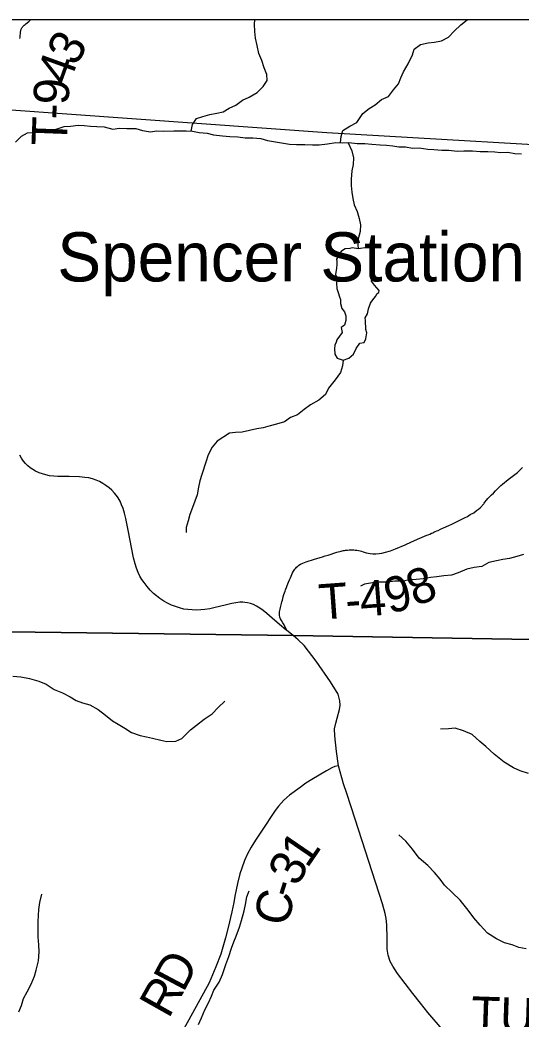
# Model space of a CAD drawing. Extents: x 0 to 191, y 0 to 55.
# Drawn here: x 148.062 to 148.465, y 24.615 to 25.418 of the extents above; entities that cross this region are included whole.
import ezdxf

# ---------------------------------------------------------------- set-up
doc = ezdxf.new("R2010")
doc.units = 0
for name, color, linetype in [('GM_X_Corporation', 7, 'Continuous'), ('GM_X_County_Road', 7, 'Continuous'), ('GM_X_County_Road_Text', 7, 'Continuous'), ('GM_X_Minor_Lake', 7, 'Continuous'), ('GM_X_Minor_River', 7, 'Continuous'), ('GM_X_Rail_Line', 7, 'Continuous'), ('GM_X_State_Route', 7, 'Continuous'), ('GM_X_Township_Road', 7, 'Continuous'), ('GM_X_Township_Road_Text', 7, 'Continuous'), ('GM_X_Unincorporated_Text', 7, 'Continuous')]:
    doc.layers.add(name, color=color, linetype=linetype)

msp = doc.modelspace()

# ---------------------------------------------------------------- linework, layer by layer
at = {"layer": 'GM_X_Corporation'}
for points in [[(146.55017, 24.94381), (147.26754, 24.93877), (147.27778, 24.93895), (147.33325, 24.9381), (147.71375, 24.93167), (147.72683, 24.93293), (148.03596, 24.92652), (148.05398, 24.9263), (148.28203, 24.9234), (148.74489, 24.91553), (149.14623, 24.90673), (149.30463, 24.90606), (149.33711, 24.90479), (149.37935, 24.90341), (149.41066, 24.90327), (149.52108, 24.90171), (149.5632, 24.9013), (149.56403, 24.95266), (149.56439, 24.97481), (149.56443, 24.97656), (149.5758, 25.41761), (143.27549, 25.41761)], [(146.55017, 24.94381), (147.26754, 24.93877), (147.27778, 24.93895), (147.33325, 24.9381), (147.71375, 24.93167), (147.72683, 24.93293), (148.03596, 24.92652), (148.05398, 24.9263), (148.28203, 24.9234), (148.74489, 24.91553), (149.14623, 24.90673), (149.30463, 24.90606), (149.33711, 24.90479), (149.37935, 24.90341), (149.41066, 24.90327), (149.52108, 24.90171), (149.5632, 24.9013), (149.56403, 24.95266), (149.56439, 24.97481), (149.56443, 24.97656), (149.5758, 25.41761), (145.79254, 25.41761)], [(149.53125, 23.09862), (149.53701, 23.54415), (149.54051, 23.67987), (149.54392, 24.0583), (149.55552, 24.46365), (149.55619, 24.51706), (149.55762, 24.60839), (149.56277, 24.77497), (149.56382, 24.82501), (149.56492, 24.82957), (149.5632, 24.9013), (149.52108, 24.90171), (149.41066, 24.90327), (149.37935, 24.90341), (149.33711, 24.90479), (149.30463, 24.90606), (149.14623, 24.90673), (148.74489, 24.91553), (148.28203, 24.9234), (148.05398, 24.9263)], [(148.05398, 24.9263), (148.28203, 24.9234), (148.74489, 24.91553), (149.14623, 24.90673), (149.30463, 24.90606), (149.33711, 24.90479), (149.37935, 24.90341), (149.41066, 24.90327), (149.52108, 24.90171), (149.5632, 24.9013), (149.56492, 24.82957), (149.56382, 24.82501), (149.56277, 24.77497), (149.55762, 24.60839), (149.55619, 24.51706), (149.55552, 24.46365), (149.54392, 24.0583), (149.54051, 23.67987), (149.53701, 23.54415), (149.53125, 23.09862)]]:
    msp.add_lwpolyline(points, dxfattribs=at)
at = {"layer": 'GM_X_County_Road'}
msp.add_lwpolyline([(148.31822, 24.81862), (148.31553, 24.81811), (148.3131, 24.81703), (148.30871, 24.81459), (148.30272, 24.81112), (148.29685, 24.80765), (148.29197, 24.80459), (148.28747, 24.80132), (148.27908, 24.79516), (148.27453, 24.79099), (148.27023, 24.78611), (148.26733, 24.78264), (148.25655, 24.76606), (148.25175, 24.75895), (148.2482, 24.75324), (148.24534, 24.74799), (148.24286, 24.7425), (148.24059, 24.73658), (148.23918, 24.732), (148.23716, 24.72406), (148.23517, 24.71389), (148.23422, 24.70893), (148.23265, 24.70132), (148.22972, 24.68867), (148.22769, 24.68045), (148.22385, 24.66751), (148.21992, 24.65734), (148.21434, 24.6444), (148.20115, 24.62009), (148.19102, 24.60199)], dxfattribs=at)
at = {"layer": 'GM_X_Minor_Lake'}
for points in [[(148.33455, 25.23381), (148.32925, 25.23469), (148.32736, 25.2341), (148.32358, 25.23386), (148.32226, 25.2329), (148.32058, 25.23155), (148.31927, 25.23001), (148.31815, 25.22772), (148.31666, 25.22543), (148.31706, 25.22354), (148.31708, 25.22145), (148.31673, 25.21841), (148.31603, 25.21309), (148.31719, 25.21026), (148.31686, 25.20627), (148.31709, 25.20191), (148.31807, 25.1987), (148.31905, 25.1953), (148.32002, 25.19303), (148.31986, 25.18999), (148.32103, 25.18602), (148.32314, 25.1832), (148.32412, 25.17999), (148.32416, 25.1762), (148.32306, 25.17258), (148.32137, 25.17123), (148.32062, 25.17065), (148.32123, 25.16667), (148.31918, 25.1638), (148.31694, 25.16074), (148.31639, 25.15884), (148.31546, 25.15655), (148.31511, 25.1537), (148.31535, 25.14915), (148.31727, 25.14614), (148.32221, 25.14449)], [(148.32221, 25.14449), (148.32654, 25.14606), (148.3303, 25.14914), (148.33252, 25.15391), (148.33551, 25.15794), (148.33891, 25.15855), (148.34039, 25.16141), (148.3411, 25.16635), (148.34031, 25.169), (148.34005, 25.17621), (148.33984, 25.17848), (148.3417, 25.18173), (148.34242, 25.18553), (148.34408, 25.1901), (148.34519, 25.19183), (148.34706, 25.19431), (148.34799, 25.19546), (148.34948, 25.19795), (148.3508, 25.19872), (148.35097, 25.20043), (148.34733, 25.20475), (148.34484, 25.20776), (148.34575, 25.21137), (148.34611, 25.21327), (148.34685, 25.21556), (148.34737, 25.21955), (148.34734, 25.22315), (148.34711, 25.22694), (148.34651, 25.23016), (148.3465, 25.23168), (148.34573, 25.23281), (148.34324, 25.23505), (148.34098, 25.23484), (148.33455, 25.23381)]]:
    msp.add_lwpolyline(points, dxfattribs=at)
at = {"layer": 'GM_X_Minor_River'}
for points in [[(148.20003, 25.32835), (148.20092, 25.33364), (148.20428, 25.33842), (148.20937, 25.34019), (148.21484, 25.34159), (148.22069, 25.3428), (148.2256, 25.34381), (148.23049, 25.34672), (148.23596, 25.34925), (148.24122, 25.35311), (148.24649, 25.35564), (148.25307, 25.35933), (148.25794, 25.36413), (148.26092, 25.3691), (148.26087, 25.37384), (148.25874, 25.37912), (148.25679, 25.38517), (148.25446, 25.39064), (148.25307, 25.39708), (148.25169, 25.40313), (148.25107, 25.40843), (148.25082, 25.41431), (148.25118, 25.41761)], [(148.31996, 25.31912), (148.3206, 25.32393), (148.32187, 25.32888), (148.32732, 25.33236), (148.33316, 25.33528), (148.33782, 25.34255), (148.34289, 25.3464), (148.34777, 25.3495), (148.35303, 25.35374), (148.35849, 25.35627), (148.3626, 25.36144), (148.36653, 25.36642), (148.36837, 25.37119), (148.37059, 25.37596), (148.37431, 25.38245), (148.37784, 25.38951), (148.37911, 25.39427), (148.38418, 25.39794), (148.39042, 25.39915), (148.39552, 25.39979), (148.40099, 25.4008), (148.40683, 25.40372), (148.41132, 25.40871), (148.41676, 25.41371), (148.42178, 25.41761)], [(148.05878, 25.31953), (148.06365, 25.32434), (148.06854, 25.32705), (148.07573, 25.32752), (148.08159, 25.32817), (148.08707, 25.32862), (148.09235, 25.3302), (148.09801, 25.33198), (148.10312, 25.33223), (148.10916, 25.33306), (148.11408, 25.33275), (148.1192, 25.33243), (148.12412, 25.33211), (148.12999, 25.33181), (148.13701, 25.33), (148.14249, 25.33063), (148.14816, 25.33051), (148.15554, 25.33042), (148.16086, 25.32878), (148.1673, 25.32791), (148.17221, 25.32854), (148.17808, 25.32842), (148.18602, 25.32871), (148.19094, 25.32858), (148.19605, 25.32846), (148.20097, 25.32833), (148.20628, 25.32726), (148.21272, 25.32658), (148.21803, 25.32531), (148.22504, 25.32464), (148.23091, 25.32415), (148.23735, 25.32366), (148.24341, 25.32297), (148.24946, 25.32286), (148.2559, 25.32237), (148.26122, 25.32073), (148.27903, 25.31792), (148.28471, 25.31761), (148.29133, 25.3175), (148.29739, 25.31738), (148.30269, 25.31745), (148.30949, 25.3181), (148.31629, 25.31933), (148.32178, 25.31901), (148.3267, 25.31908), (148.33333, 25.3184), (148.33938, 25.31828), (148.34525, 25.31779), (148.35188, 25.3173), (148.3568, 25.31717), (148.36191, 25.31667), (148.36684, 25.31578), (148.37214, 25.31565), (148.37783, 25.31459), (148.38312, 25.31484), (148.39014, 25.31379), (148.39506, 25.31347), (148.4013, 25.31317), (148.40698, 25.31305), (148.4138, 25.31219), (148.4191, 25.31263), (148.42591, 25.31253), (148.43216, 25.31203), (148.43821, 25.31192), (148.44389, 25.3118), (148.44863, 25.3111), (148.45449, 25.31136), (148.45999, 25.31029), (148.46529, 25.31017)], [(148.32613, 25.31907), (148.32903, 25.31247), (148.33041, 25.30698), (148.33009, 25.30167), (148.32901, 25.29634), (148.32851, 25.2897), (148.32856, 25.28457), (148.32899, 25.27946), (148.3298, 25.27416), (148.33098, 25.26924), (148.33331, 25.26377), (148.33507, 25.2581), (148.33606, 25.25318), (148.33574, 25.24767), (148.33428, 25.24196), (148.33397, 25.23589), (148.33455, 25.23381)], [(148.32221, 25.14449), (148.3215, 25.13974), (148.31985, 25.1344), (148.31575, 25.12866), (148.31033, 25.12195), (148.30792, 25.1168), (148.30248, 25.11218), (148.29589, 25.10849), (148.29063, 25.10482), (148.28538, 25.10039), (148.27991, 25.09824), (148.27503, 25.09495), (148.26862, 25.09298), (148.26352, 25.09177), (148.25786, 25.09), (148.25276, 25.08917), (148.24691, 25.08796), (148.24106, 25.08656), (148.23557, 25.0863), (148.23066, 25.08567), (148.22088, 25.07948), (148.21696, 25.0745), (148.21362, 25.06838), (148.21178, 25.06248), (148.20848, 25.05257), (148.20701, 25.04762), (148.20574, 25.04229), (148.20467, 25.03639), (148.20302, 25.03125), (148.20099, 25.0261), (148.19896, 25.02057), (148.1975, 25.01543), (148.19585, 25.0101), (148.1959, 25.00592)], [(148.46701, 24.98843), (148.46154, 24.98665), (148.45569, 24.98506), (148.4504, 24.98443), (148.44531, 24.98323), (148.43926, 24.98201), (148.43343, 24.97872), (148.42739, 24.97788), (148.42135, 24.97648), (148.41437, 24.97373), (148.4091, 24.97177), (148.40286, 24.97131), (148.39738, 24.9703), (148.39228, 24.96985), (148.38642, 24.96883), (148.38075, 24.96819), (148.37527, 24.96793), (148.37036, 24.96692), (148.36355, 24.96684), (148.35788, 24.9662), (148.35069, 24.96611), (148.34578, 24.96548), (148.33935, 24.96445), (148.33596, 24.96289)], [(148.05672, 24.89067), (148.06317, 24.89012), (148.07, 24.88882), (148.0776, 24.88675), (148.08348, 24.88412), (148.08994, 24.87996), (148.09659, 24.87732), (148.10286, 24.87412), (148.10761, 24.87109), (148.11274, 24.86921), (148.11843, 24.86752), (148.12527, 24.86394), (148.13116, 24.85921), (148.13667, 24.85467), (148.14142, 24.85203), (148.14655, 24.84882), (148.15206, 24.84542), (148.15909, 24.84297), (148.16403, 24.84204), (148.16896, 24.84092), (148.1756, 24.83923), (148.18035, 24.8383), (148.18756, 24.83851), (148.19249, 24.84062), (148.19949, 24.84767), (148.20422, 24.85129), (148.21047, 24.85606), (148.21672, 24.86026), (148.22164, 24.86541), (148.22694, 24.87055)], [(148.47106, 24.8125), (148.46423, 24.81457), (148.45891, 24.81702), (148.4515, 24.82155), (148.44352, 24.82798), (148.43667, 24.83423), (148.43192, 24.8382), (148.42583, 24.84388), (148.41881, 24.8467), (148.41197, 24.84877), (148.40685, 24.84837), (148.40021, 24.84797)], [(148.46914, 24.67173), (148.46325, 24.67285), (148.45794, 24.67493), (148.45167, 24.67642), (148.4454, 24.67963), (148.43818, 24.68417), (148.43228, 24.6908), (148.42715, 24.69667), (148.42258, 24.70273), (148.41611, 24.71069), (148.40964, 24.71694), (148.40356, 24.72281), (148.39994, 24.72774), (148.39537, 24.73285), (148.39005, 24.73853), (148.3832, 24.74458), (148.37787, 24.7516), (148.37254, 24.75804), (148.36684, 24.76315)], [(148.06155, 24.62116), (148.06363, 24.62629), (148.06532, 24.63181), (148.06815, 24.63714), (148.07136, 24.64323), (148.07419, 24.6497), (148.07551, 24.65445), (148.0772, 24.66205), (148.07775, 24.66927), (148.07754, 24.67478), (148.07715, 24.68143), (148.07695, 24.68618), (148.07712, 24.69359), (148.0773, 24.69834), (148.07766, 24.70328), (148.07841, 24.70898), (148.07991, 24.71563)], [(148.21388, 24.62832), (148.21633, 24.63365), (148.21822, 24.63841), (148.22257, 24.64488), (148.22521, 24.65116), (148.22784, 24.65896), (148.23029, 24.66561), (148.23236, 24.67208), (148.23425, 24.67722), (148.23613, 24.68197), (148.23877, 24.68901), (148.24028, 24.69452), (148.24253, 24.70213), (148.24366, 24.70726), (148.24478, 24.71353), (148.24648, 24.71829)], [(148.20596, 24.61082), (148.20822, 24.61615), (148.21086, 24.62261), (148.21388, 24.62832)]]:
    msp.add_lwpolyline(points, dxfattribs=at)
at = {"layer": 'GM_X_Rail_Line'}
msp.add_lwpolyline([(148.05172, 25.3458), (148.3091, 25.32736), (148.55775, 25.3129), (148.62149, 25.30793), (148.65702, 25.30663), (148.71395, 25.30367), (148.76064, 25.2974), (148.7932, 25.29174), (148.82913, 25.28021), (148.85533, 25.2712), (148.88734, 25.25727), (148.91878, 25.23506), (148.93909, 25.21978), (148.96709, 25.19371), (148.99213, 25.16425), (149.01185, 25.13777), (149.04173, 25.10389)], dxfattribs=at)
at = {"layer": 'GM_X_State_Route'}
for points in [[(148.2768, 24.92737), (148.27606, 24.92793), (148.27101, 24.93209), (148.26514, 24.93718), (148.2607, 24.94104), (148.25779, 24.94332), (148.25501, 24.94526), (148.25239, 24.94686), (148.24993, 24.9481), (148.24766, 24.94898), (148.24531, 24.94961), (148.24321, 24.94992), (148.2414, 24.95003), (148.23896, 24.94997), (148.23591, 24.94963), (148.23258, 24.94901), (148.22717, 24.94767), (148.21933, 24.94569), (148.21505, 24.94479), (148.21104, 24.94416), (148.20761, 24.94382), (148.20448, 24.9437), (148.20073, 24.94378), (148.1973, 24.94408), (148.19421, 24.94454), (148.19055, 24.94541), (148.18728, 24.94647), (148.18408, 24.94775), (148.18098, 24.94924), (148.17798, 24.95092), (148.17485, 24.95297), (148.17211, 24.95505), (148.16974, 24.95709), (148.16708, 24.95972), (148.1646, 24.96252), (148.16211, 24.96573), (148.16035, 24.96831), (148.15876, 24.97101), (148.15738, 24.97383), (148.15603, 24.97733), (148.15492, 24.98092), (148.15376, 24.98577), (148.15212, 24.99401), (148.14974, 25.00652), (148.14759, 25.01716), (148.14647, 25.02166), (148.14536, 25.02519), (148.14413, 25.02834), (148.14281, 25.03111), (148.1413, 25.03378), (148.13992, 25.0358), (148.1384, 25.03772), (148.13627, 25.03992), (148.13396, 25.04193), (148.13149, 25.04376), (148.1289, 25.04541), (148.12619, 25.04686), (148.12368, 25.048), (148.12079, 25.04903), (148.11782, 25.04979), (148.11449, 25.0503), (148.11019, 25.05063), (148.10182, 25.05089), (148.09281, 25.05104), (148.08968, 25.05122), (148.08626, 25.05163), (148.08319, 25.05226), (148.08047, 25.05303), (148.07781, 25.054), (148.07497, 25.05533), (148.07278, 25.05655), (148.07069, 25.05796), (148.06874, 25.05957), (148.06696, 25.06135), (148.06533, 25.06328), (148.0637, 25.0656), (148.06228, 25.06804)], [(148.28213, 24.92313), (148.27927, 24.9255), (148.2768, 24.92737)], [(148.40171, 24.60717), (148.39009, 24.62065), (148.38417, 24.62801), (148.37819, 24.63585), (148.36588, 24.65181), (148.36196, 24.65765), (148.35982, 24.66144), (148.35817, 24.66653), (148.35755, 24.67134), (148.35742, 24.68001), (148.35714, 24.69101), (148.35673, 24.69596), (148.35597, 24.69995), (148.35377, 24.70772), (148.34263, 24.74184), (148.33183, 24.77588), (148.32502, 24.79651), (148.32241, 24.80422), (148.31822, 24.81862), (148.31671, 24.83005), (148.31532, 24.84279), (148.31523, 24.84842), (148.3161, 24.85284), (148.31723, 24.85683), (148.31922, 24.86393), (148.31974, 24.8674), (148.31948, 24.87095), (148.31801, 24.87624), (148.31203, 24.88603), (148.30033, 24.90276), (148.29088, 24.91524), (148.28584, 24.91979), (148.28213, 24.92313)]]:
    msp.add_lwpolyline(points, dxfattribs=at)
at = {"layer": 'GM_X_Township_Road'}
for points in [[(148.0623, 25.40276), (148.06247, 25.40371), (148.06266, 25.40518), (148.06277, 25.40667), (148.06282, 25.40716), (148.06286, 25.40769), (148.06294, 25.40823), (148.06302, 25.40877), (148.06311, 25.40916), (148.06321, 25.40951), (148.06333, 25.40986), (148.06346, 25.41022), (148.0637, 25.41075), (148.06404, 25.4113), (148.0644, 25.41183), (148.06478, 25.41228), (148.06505, 25.41257), (148.0653, 25.41282), (148.06559, 25.41312), (148.06584, 25.41336), (148.06656, 25.41396), (148.06719, 25.41447), (148.06963, 25.41647), (148.07096, 25.41761)], [(148.2768, 24.92737), (148.27579, 24.92963), (148.27534, 24.93056), (148.27457, 24.93194), (148.27366, 24.9335), (148.27245, 24.9353), (148.27175, 24.93667), (148.27124, 24.93813), (148.27098, 24.93965), (148.27094, 24.94048), (148.27095, 24.94151), (148.27102, 24.94237), (148.27116, 24.94336), (148.27139, 24.94454), (148.27167, 24.94578), (148.27195, 24.94689), (148.27249, 24.94888), (148.27291, 24.95041), (148.27324, 24.95164), (148.27364, 24.95308), (148.27401, 24.9544), (148.27455, 24.9561), (148.27498, 24.95748), (148.27543, 24.9589), (148.27584, 24.96005), (148.27649, 24.96177), (148.27717, 24.96349), (148.27821, 24.96608), (148.2791, 24.96805), (148.27968, 24.96949), (148.28024, 24.97084), (148.28088, 24.97235), (148.28148, 24.97352), (148.28215, 24.97484), (148.28275, 24.97572), (148.28333, 24.97665), (148.28396, 24.97749), (148.28473, 24.97829), (148.28562, 24.9791), (148.28661, 24.97988), (148.28794, 24.98065), (148.28961, 24.98147), (148.2925, 24.98258), (148.29902, 24.9846), (148.30556, 24.98659), (148.30764, 24.98719), (148.31002, 24.98788), (148.3171, 24.99014), (148.3204, 24.99111), (148.32204, 24.99147), (148.32308, 24.99164), (148.32407, 24.99178), (148.32551, 24.9919), (148.32694, 24.99198), (148.32853, 24.99203), (148.33055, 24.99201), (148.33173, 24.99195), (148.33301, 24.99184), (148.33439, 24.99163), (148.33584, 24.99126), (148.33678, 24.99096), (148.33804, 24.99055), (148.34067, 24.98976), (148.34208, 24.98936), (148.34366, 24.98905), (148.34597, 24.98889), (148.34836, 24.98888), (148.35105, 24.98908), (148.35315, 24.98946), (148.35614, 24.99023), (148.36, 24.99141), (148.36407, 24.99292), (148.3718, 24.99618), (148.37691, 24.99844), (148.38373, 25.00139), (148.38937, 25.00375), (148.39049, 25.00426), (148.39161, 25.00475), (148.39302, 25.00538), (148.39413, 25.00588), (148.39498, 25.00625), (148.39611, 25.00674), (148.39724, 25.00724), (148.39837, 25.00773), (148.40033, 25.00862), (148.40283, 25.00976), (148.40698, 25.01165), (148.40945, 25.01277), (148.41159, 25.01382), (148.41579, 25.01594), (148.41804, 25.01701), (148.41968, 25.0178), (148.42193, 25.01898), (148.42421, 25.02034), (148.42695, 25.02194), (148.42935, 25.02355), (148.43092, 25.02476), (148.43225, 25.02594), (148.43298, 25.02665), (148.43343, 25.02716), (148.4338, 25.02763), (148.43416, 25.02806), (148.43464, 25.02862), (148.43504, 25.02913), (148.43543, 25.02967), (148.43597, 25.03034), (148.43726, 25.03189), (148.43845, 25.03324), (148.43925, 25.03401), (148.44001, 25.0349), (148.44126, 25.03623), (148.44281, 25.03772), (148.44447, 25.03953), (148.44714, 25.04212), (148.44874, 25.04364), (148.45015, 25.04485), (148.45474, 25.04846), (148.45792, 25.05094), (148.46205, 25.05423), (148.46412, 25.05609), (148.46625, 25.05834)]]:
    msp.add_lwpolyline(points, dxfattribs=at)

# ---------------------------------------------------------------- texts
at = {"layer": 'GM_X_County_Road_Text'}
for s, height, rotation, p in [('1', 0.02841, 55.66621, (148.29316, 24.7356)), ('3', 0.02841, 61.9826, (148.28537, 24.72086)), ('-', 0.02841, 72.5426, (148.2824, 24.71101)), ('C', 0.02841, 77.89243, (148.27769, 24.68887)), ('D', 0.02841, 62.04799, (148.19362, 24.6359)), ('R', 0.02841, 60.6516, (148.18183, 24.61491)), ('TUCKAHOE', 0.028409, 358.12412, (148.42455, 24.60519))]:
    msp.add_text(s, height=height, rotation=rotation, dxfattribs=at).set_placement(p)
at = {"layer": 'GM_X_Township_Road_Text'}
for s, rotation, p in [('3', 60.71339, (148.10728, 25.37962)), ('4', 70.24185, (148.10188, 25.36428)), ('9', 86.79274, (148.10133, 25.34893)), ('-', 87.603, (148.10085, 25.33738)), ('T', 87.77944, (148.10003, 25.31617)), ('8', 22.40046, (148.38029, 24.94627)), ('4', 4.49089, (148.33649, 24.9384)), ('9', 14.09208, (148.35905, 24.94061)), ('T', 4.18851, (148.3035, 24.93597)), ('-', 4.24568, (148.32472, 24.93753))]:
    msp.add_text(s, height=0.02841, rotation=rotation, dxfattribs=at).set_placement(p)
at = {"layer": 'GM_X_Unincorporated_Text'}
msp.add_text('Spencer Station', height=0.0394886, rotation=0.00001, dxfattribs=at).set_placement((148.0924, 25.20763))

doc.saveas('drawing.dxf')
